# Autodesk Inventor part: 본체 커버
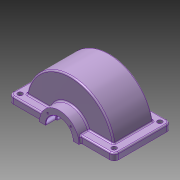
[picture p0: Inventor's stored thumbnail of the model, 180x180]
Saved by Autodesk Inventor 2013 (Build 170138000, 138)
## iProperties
Created: 2023-06
Part Number: 본체 커버
Material: 알루미늄 6061
Document SubType Name: Modeling
Designer: mdu-01
Density: 1 g/cm^3
Author: mdu-01
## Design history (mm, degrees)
sketch "스케치1"
  geometry: L1 (0, 70)-(0, -70); L2 (0, 70)-(45, 70); L3 (45, 70)-(45, 45); L4 (45, 45)-(100, 45); L5 (0, 0)-(100, 0); L6 (0, -70)-(45, -70); L7 (45, -70)-(45, -45); L8 (45, -45)-(100, -45); L9 (100, 45)-(100, -45); 1 further point
  constraints: 18 end point, 3 perpendicular, 3 symmetric about line, 2 midpoint, 2 parallel, 1 coincident, 1 vertical
  dimensions: "d0" = 140 distance of L1.start L1.end; "d1" = 90 diameter of L3 L1; "d2" = 90 distance between parallel lines of L8 L4; "d3" = 200 diameter of L9 L1
revolve "회전1" sketch "스케치1" stored, may be unused: angle "d4" = 180 deg
sketch "스케치2"
  geometry: L1 (-10, -110)-(210, -110); L2 (220, -100)-(220, 10); L3 (210, 20)-(-10, 20); L4 (-20, 10)-(-20, -100); L5 (-20, -110)-(220, 20); L6 (220, -110)-(-20, 20); A1 r 10 centre (-10, 10) between (-10, 20) and (-20, 10); A2 r 10 centre (210, 10) between (220, 10) and (210, 20); A3 r 10 centre (210, -100) between (210, -110) and (220, -100); A4 r 10 centre (-10, -100) between (-20, -100) and (-10, -110); 1 further point
  constraints: 12 end point, 8 point on circle, 8 point on line, 8 tangent, 4 centre point, 3 equal radius, 2 midpoint, 2 parallel, 1 horizontal, 1 perpendicular
  dimensions: "d5" = 240 distance of L6.end L5.end; "d6" = 130 distance of L5.end L6.start; "d7" = 10 radius of A1
extrude "돌출1" join sketch "스케치2" distance "d8" = 15; taper "d9" = 0 deg
sketch "스케치3"
  geometry: L1 (0, 70)-(45, 70) reference; L2 (0, -70)-(45, -70) reference; L3 (0, 70)-(0, -70); L4 (31, 70)-(31, 48); L5 (30, 47)-(27.5, 47); L6 (27.5, 47)-(27.5, 32); L7 (27.5, 32)-(87, 32); L8 (0, 0)-(92.097, 0); L9 (31, -70)-(31, -48); L10 (30, -47)-(27.5, -47); L11 (27.5, -47)-(27.5, -32); L12 (27.5, -32)-(87, -32); L13 (87, 32)-(87, -32); L14 (0, 70)-(31, 70); L15 (0, -70)-(31, -70); A1 r 1 centre (30, 48) between (30, 47) and (31, 48); A2 r 1 centre (30, -48) between (31, -48) and (30, -47); 2 further points
  constraints: 26 end point, 5 point on line, 5 symmetric about line, 4 parallel, 4 point on circle, 4 tangent, 3 perpendicular, 2 centre point, 2 collinear, 1 equal radius
  dimensions: "d10" = 1 radius of A1; "d11" = 62 diameter of L4 L3; "d12" = 23 distance between parallel lines of L1 L5; "d13" = 64 distance between parallel lines of L12 L7; "d14" = 55 diameter of L6 L3; "d15" = 87 distance between parallel lines of L13 L3
revolve "회전2" sketch "스케치3" stored, may be unused: angle "d16" = 180 deg
fillet "모깎기1" dims "d17" = 3
fillet "모깎기2" dims "d18" = 3
sketch "스케치4"
  geometry: L1 (-7, -7)-(207, -7); L2 (207, -7)-(207, 97); L3 (207, 97)-(-7, 97); L4 (-7, 97)-(-7, -7); L5 (-7, -7)-(207, 97); L6 (207, -7)-(-7, 97); 1 further point
  constraints: 12 end point, 2 midpoint, 2 parallel, 1 horizontal, 1 perpendicular
  dimensions: "d19" = 214 distance of L3.end L2.end; "d20" = 104 distance of L2.end L1.end
hole "구멍1" sketch "스케치4" at (207, -7), (-7, -7), (207, 97), (-7, 97) diameter "d21" = 6.6; stored, may be unused: countersink angle "d25" = 90 deg, drill point angle "d27" = 118 deg; dims "d22" = 6, "d23" = 11, "d24" = 6.8, "d26" = 8
sketch "스케치5"
  geometry: L1 (-26.163, 26.163)-(26.163, 26.163); L2 (26.163, 26.163)-(26.163, -26.163); L3 (26.163, -26.163)-(-26.163, -26.163); L4 (-26.163, -26.163)-(-26.163, 26.163); A1 r 37 centre (0, 0) between (-26.163, 26.163) and (26.163, -26.163); 1 further point
  constraints: 8 end point, 3 point on circle, 2 parallel, 2 perpendicular, 1 centre point, 1 coincident, 1 horizontal
  dimensions: "d28" = 74 diameter of A1
hole "구멍2" sketch "스케치5" at (-26.163, 26.163), (26.163, 26.163) diameter "d29" = 4.134; stored, may be unused: countersink angle "d33" = 90 deg, drill point angle "d35" = 118 deg; dims "d30" = 10, "d31" = 11, "d32" = 6.8, "d34" = 12
chamfer "모따기1" distance "d36" = 1; stored, may be unused: second distance "d37" = 2, angle "d38" = 45 deg
node "솔리드1"
mirror "대칭1"
